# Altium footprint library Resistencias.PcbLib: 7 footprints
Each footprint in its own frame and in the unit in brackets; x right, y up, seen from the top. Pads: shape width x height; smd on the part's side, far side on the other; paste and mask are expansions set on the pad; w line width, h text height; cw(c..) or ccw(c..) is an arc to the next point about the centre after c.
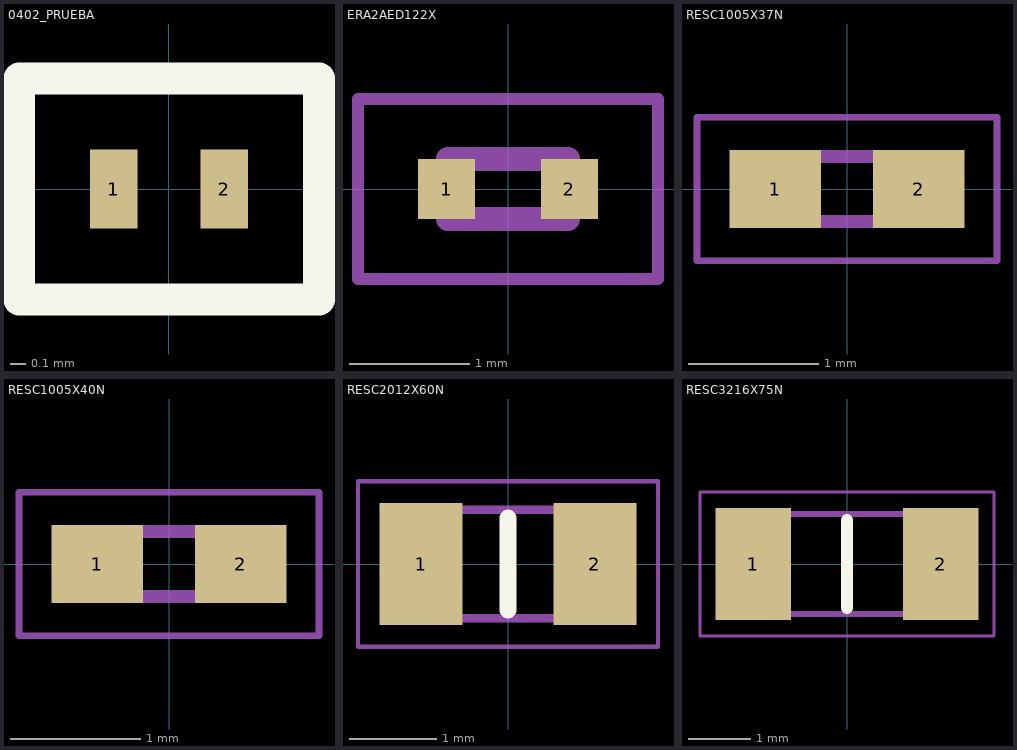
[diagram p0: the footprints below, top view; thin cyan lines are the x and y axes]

## 0402_PRUEBA [mm]
pads (2):
  rect 0.3x0.5 smd: 1(-0.35,0) 2(0.35,0)
Top Overlay:
  lines w0.2: -0.95,-0.7 0.95,-0.7 0.95,0.7 -0.95,0.7 -0.95,0 -0.95,-0.7
3D body: height 0.25, standoff 0, extent -0.254,-0.254 0.254,0.254
3D body: height 0.25, standoff 0, extent 0.254,-0.254 0.381,0.254
3D body: height 0.25, standoff 0, extent -0.381,-0.254 -0.254,0.254

## ERA2AED122X [mm]
pads (2):
  rect 0.475x0.5 smd: 1(-0.512,0) 2(0.512,0)
Mechanical 13:
  lines w0.2: -0.5,-0.25 -0.5,0.25 0.5,0.25 0.5,-0.25 -0.5,-0.25
Mechanical 15:
  lines w0.1: -1.25,-0.75 -1.25,0.75 1.25,0.75 1.25,-0.75 -1.25,-0.75
3D body "ERA-2ARC102X.stp": height 0.35, standoff 0, extent -0.5,-0.25 0.5,0.25

## PCBComponent_1 [mm]

## RESC1005X37N [mm]
pads (2):
  rect 0.7x0.6 smd: 1(-0.55,0) 2(0.55,0)
Mechanical 13:
  lines w0.1: -0.5,-0.25 -0.5,0.25 0.5,0.25 0.5,-0.25 -0.5,-0.25
Mechanical 15:
  lines w0.05: -1.15,-0.55 -1.15,0.55 1.15,0.55 1.15,-0.55 -1.15,-0.55
3D body "MCS04020C4701FE000.stp": height 0.32, standoff 0, extent -0.5,-0.25 0.5,0.25

## RESC1005X40N [mm]
pads (2):
  rect 0.7x0.6 smd: 1(-0.55,0) 2(0.55,0)
Mechanical 13:
  lines w0.1: -0.512,-0.25 -0.512,0.25 0.512,0.25 0.512,-0.25 -0.512,-0.25
Mechanical 15:
  lines w0.05: -1.15,-0.55 -1.15,0.55 1.15,0.55 1.15,-0.55 -1.15,-0.55
3D body "RK73B1ETTP103J.stp": height 0.4, standoff 0, extent -0.513,-0.25 0.513,0.25

## RESC2012X60N [mm]
pads (2):
  rect 0.95x1.4 smd: 1(-1,0) 2(1,0)
Top Overlay:
  lines w0.2: 0,-0.525 0,0.525
Mechanical 13:
  lines w0.1: -1,-0.625 -1,0.625 1,0.625 1,-0.625 -1,-0.625
Mechanical 15:
  lines w0.05: -1.725,-0.95 -1.725,0.95 1.725,0.95 1.725,-0.95 -1.725,-0.95
3D body "RK73H2ATTD2212F.stp": height 0.6, standoff 0, extent -1,-0.625 1,0.625

## RESC3216X75N [mm]
pads (2):
  rect 1.2x1.8 smd: 1(-1.5,0) 2(1.5,0)
Top Overlay:
  lines w0.2: 0,-0.7 0,0.7
Mechanical 13:
  lines w0.1: -1.6,-0.8 -1.6,0.8 1.6,0.8 1.6,-0.8 -1.6,-0.8
Mechanical 15:
  lines w0.05: -2.35,-1.15 -2.35,1.15 2.35,1.15 2.35,-1.15 -2.35,-1.15
3D body "CR1206-J_-000ELF.stp": height 0.75, standoff 0, extent -1.6,-0.8 1.6,0.8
